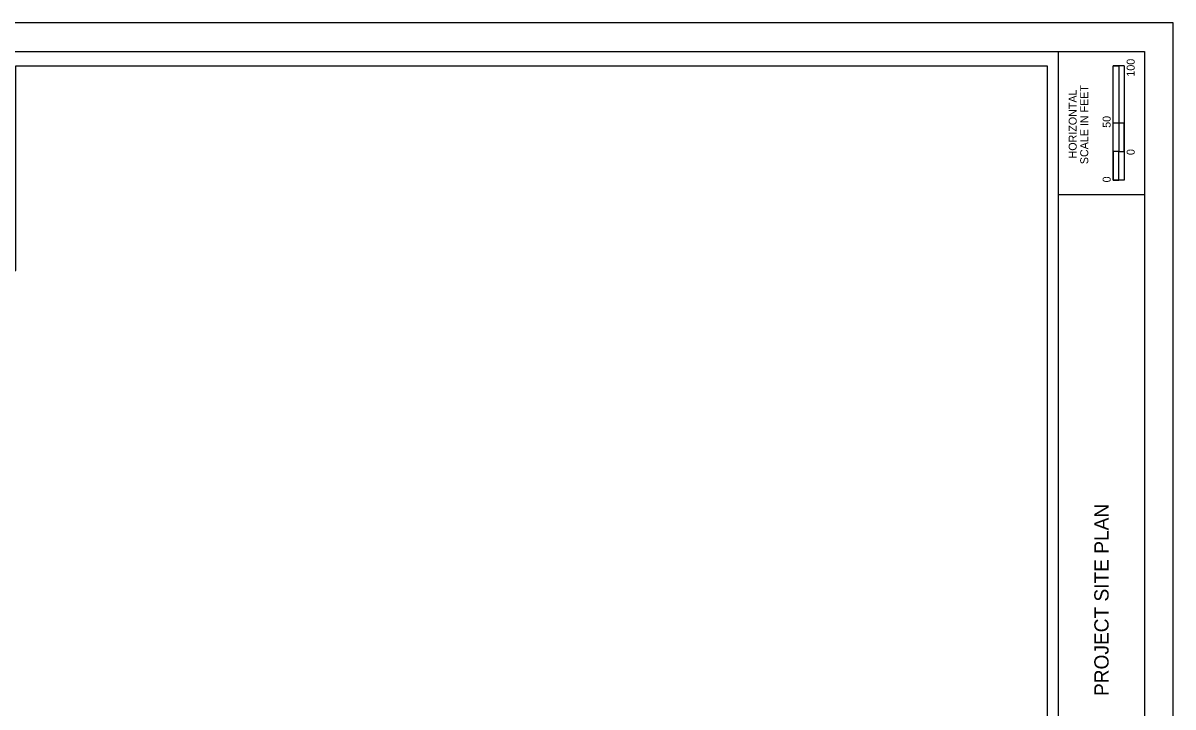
# Model space of a CAD drawing. Extents: x 0 to 1700, y 0 to 1100.
# Drawn here: x 695 to 1700, y 502 to 1100 of the extents above; entities that cross this region are included whole.
import ezdxf

# ---------------------------------------------------------------- set-up
doc = ezdxf.new("R2010")
doc.units = 0
for name, color, linetype in [('DT_X_Contour_Major', 7, 'Continuous'), ('DT_X_Contour_Minor', 7, 'Continuous'), ('DT_X_Terrain_Ground_Line', 7, 'Continuous'), ('DT_X_Triangles', 7, 'Continuous')]:
    doc.layers.add(name, color=color, linetype=linetype)

msp = doc.modelspace()

# ---------------------------------------------------------------- linework, layer by layer
at = {"layer": 'DT_X_Contour_Major'}
msp.add_lwpolyline([(85, 883.5), (688.3, 883.5), (688.3, 1062.5), (1590, 1062.5), (1590, 257.4), (593.3, 257.4), (593.3, 340.4), (85, 340.4)], close=True, dxfattribs=at)
at = {"layer": 'DT_X_Contour_Minor'}
for p, q in [((1600, 25), (1600, 1075)), ((1600, 950), (1675, 950))]:
    msp.add_line(p, q, dxfattribs=at)
msp.add_lwpolyline([(75, 1075), (1675, 1075), (1675, 25), (75, 25)], close=True, dxfattribs=at)
at = {"layer": 'DT_X_Terrain_Ground_Line'}
msp.add_lwpolyline([(0, 0), (1700, 0), (1700, 1100), (0, 1100)], close=True, dxfattribs=at)
at = {"layer": 'DT_X_Triangles'}
for p, q in [((1647.8, 962.5), (1647.8, 1062.5)), ((1657.2, 1062.5), (1647.8, 1062.5)), ((1647.8, 1012.5), (1647.8, 1062.5)), ((1647.8, 1062.5), (1652.5, 1062.5)), ((1652.5, 1062.5), (1652.5, 1012.5)), ((1652.5, 1062.5), (1652.5, 1062.5)), ((1657.2, 1062.5), (1657.2, 962.5)), ((1652.5, 1012.5), (1647.8, 1012.5)), ((1657.2, 1012.5), (1652.5, 1012.5)), ((1652.5, 1012.5), (1652.5, 987.5)), ((1657.2, 987.5), (1657.2, 1012.5)), ((1652.5, 987.5), (1647.8, 987.5)), ((1647.8, 987.5), (1647.8, 962.5)), ((1652.5, 987.5), (1657.2, 987.5)), ((1652.5, 962.5), (1652.5, 987.5)), ((1657.2, 962.5), (1647.8, 962.5)), ((1647.8, 962.5), (1652.5, 962.5))]:
    msp.add_line(p, q, dxfattribs=at)

# ---------------------------------------------------------------- texts
for s, height, p in [('100', 7, (1666.5, 1053.1)), ('HORIZONTAL', 7, (1615.8, 981.5)), ('SCALE IN FEET', 7, (1625.9, 976.5)), ('50', 7, (1645.5, 1008.3)), ('0', 7, (1666.5, 984.5)), ('0', 7, (1645.5, 960.6)), ('PROJECT SITE PLAN', 12.5, (1643.7, 511.3))]:
    msp.add_text(s, height=height, rotation=90, dxfattribs=at).set_placement(p)

doc.saveas('drawing.dxf')
